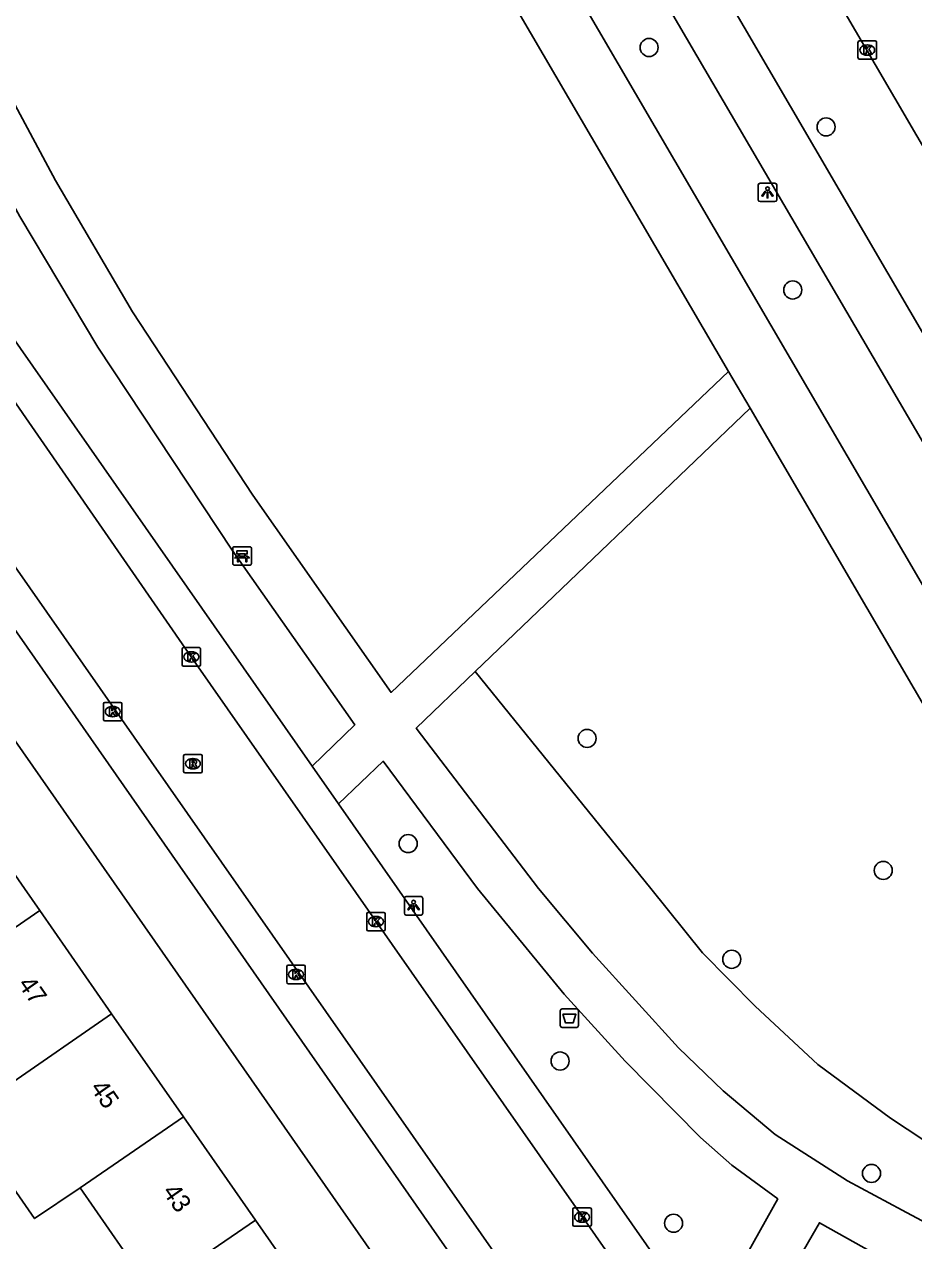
# Model space of a CAD drawing. Extents: x 159353 to 160616, y 385893 to 387321.
# Drawn here: x 159867.4 to 159915.6, y 386230.9 to 386296.8 of the extents above; entities that cross this region are included whole.
import ezdxf

# ---------------------------------------------------------------- set-up
doc = ezdxf.new("R2010")
doc.units = 0
for name, color, linetype in [('IMGEO_Afvalbak', 7, 'Continuous'), ('IMGEO_Bank', 7, 'Continuous'), ('IMGEO_Boom', 7, 'Continuous'), ('IMGEO_Fietspad_gesloten', 7, 'Continuous'), ('IMGEO_Groenvoorziening', 7, 'Continuous'), ('IMGEO_Kolk', 7, 'Continuous'), ('IMGEO_Lichtpunt', 7, 'Continuous'), ('IMGEO_Pand', 7, 'Continuous'), ('IMGEO_Pand_nummerreeks', 7, 'Continuous'), ('IMGEO_Rijbaan_lokaal_gesloten', 7, 'Continuous'), ('IMGEO_Rijbaan_lokaal_open', 7, 'Continuous'), ('IMGEO_Rioolput', 7, 'Continuous'), ('IMGEO_Voetpad_halfverhard', 7, 'Continuous'), ('IMGEO_Voetpad_open', 7, 'Continuous')]:
    doc.layers.add(name, color=color, linetype=linetype)

msp = doc.modelspace()

# ---------------------------------------------------------------- linework, layer by layer
at = {"layer": 'IMGEO_Afvalbak'}
for p, q in [((159896.459, 386242.574), (159896.459, 386243.374)), ((159896.459, 386243.374), (159896.459, 386242.574)), ((159896.559, 386243.474), (159897.349, 386243.474)), ((159897.349, 386243.474), (159896.559, 386243.474)), ((159897.449, 386243.374), (159897.449, 386242.574)), ((159897.449, 386242.574), (159897.449, 386243.374)), ((159897.349, 386242.474), (159896.559, 386242.474)), ((159896.559, 386242.474), (159897.349, 386242.474))]:
    msp.add_line(p, q, dxfattribs=at)
msp.add_lwpolyline([(159896.602, 386243.188), (159897.306, 386243.188), (159897.157, 386242.718), (159896.751, 386242.718), (159896.602, 386243.188)], dxfattribs=at)
for centre, start, end in [((159896.559, 386243.374), 90, 180), ((159896.559, 386243.374), 90, 180), ((159897.349, 386243.374), 0, 90), ((159897.349, 386243.374), 360, 90), ((159896.559, 386242.574), 180, 270), ((159896.559, 386242.574), 180, 270), ((159897.349, 386242.574), 270, 0), ((159897.349, 386242.574), 270, 0)]:
    msp.add_arc(centre, 0.1, start, end, dxfattribs=at)
at = {"layer": 'IMGEO_Bank'}
for p, q in [((159878.733, 386267.573), (159878.733, 386268.414)), ((159878.733, 386268.414), (159878.733, 386267.573)), ((159878.808, 386268.498), (159879.649, 386268.498)), ((159879.649, 386268.498), (159878.808, 386268.498)), ((159879.042, 386268.004), (159879.042, 386268.11)), ((159879.086, 386268.11), (159879.086, 386268.004)), ((159879.374, 386268.116), (159879.092, 386268.116)), ((159879.38, 386268.004), (159879.38, 386268.11)), ((159879.424, 386268.11), (159879.424, 386268.004)), ((159879.733, 386268.423), (159879.733, 386267.582)), ((159879.733, 386267.582), (159879.733, 386268.423)), ((159879.658, 386267.498), (159878.817, 386267.498)), ((159878.817, 386267.498), (159879.658, 386267.498)), ((159879.43, 386267.896), (159879.037, 386267.896)), ((159879.092, 386267.998), (159879.374, 386267.998))]:
    msp.add_line(p, q, dxfattribs=at)
for points in [[(159879.036, 386268.116), (159878.95, 386268.116), (159878.95, 386268.277), (159879.513, 386268.277), (159879.513, 386268.116), (159879.43, 386268.116)], [(159878.98, 386267.896), (159878.838, 386267.896), (159878.95, 386267.998), (159879.036, 386267.998)], [(159879.03, 386267.889), (159879.03, 386267.682), (159878.987, 386267.682), (159878.987, 386267.889)], [(159879.43, 386267.998), (159879.513, 386267.998), (159879.625, 386267.896), (159879.486, 386267.896)], [(159879.48, 386267.889), (159879.48, 386267.682), (159879.436, 386267.682), (159879.436, 386267.889)]]:
    msp.add_lwpolyline(points, dxfattribs=at)
for centre, radius, start, end in [((159878.811, 386268.42), 0.0779, 92.4484, 184.28452), ((159878.811, 386268.42), 0.0779, 92.4484, 184.28452), ((159879.035, 386268.109), 0.00671, 2.89567, 87.10433), ((159879.092, 386268.109), 0.00671, 92.89567, 177.10433), ((159879.374, 386268.109), 0.00671, 2.89567, 87.10433), ((159879.431, 386268.109), 0.00671, 92.89567, 177.10433), ((159879.655, 386268.42), 0.0779, 2.4484, 94.28452), ((159879.655, 386268.42), 0.0779, 2.4484, 94.28452), ((159878.811, 386267.576), 0.0779, 182.4484, 274.28452), ((159878.811, 386267.576), 0.0779, 182.4484, 274.28452), ((159878.98, 386267.889), 0.00671, 2.89567, 87.10433), ((159879.037, 386267.889), 0.00671, 92.89567, 177.10433), ((159879.035, 386268.005), 0.00671, 272.89567, 357.10433), ((159879.092, 386268.005), 0.00671, 182.89567, 267.10433), ((159879.374, 386268.005), 0.00671, 272.89567, 357.10433), ((159879.431, 386268.005), 0.00671, 182.89567, 267.10433), ((159879.429, 386267.889), 0.00671, 2.89567, 87.10433), ((159879.486, 386267.889), 0.00671, 92.89567, 177.10433), ((159879.655, 386267.576), 0.0779, 272.4484, 4.28452), ((159879.655, 386267.576), 0.0779, 272.4484, 4.28452)]:
    msp.add_arc(centre, radius, start, end, dxfattribs=at)
at = {"layer": 'IMGEO_Boom'}
for centre in [(159901.274, 386295.532), (159910.857, 386291.236), (159909.052, 386282.404), (159897.915, 386258.123), (159888.224, 386252.427), (159913.95, 386250.975), (159905.747, 386246.163), (159896.451, 386240.656), (159913.315, 386234.572), (159902.594, 386231.876)]:
    msp.add_circle(centre, 0.489, dxfattribs=at)
at = {"layer": 'IMGEO_Fietspad_gesloten'}
for points in [[(159847.159, 386392.191), (159854.556, 386379.293), (159862.352, 386365.974), (159919.537, 386268.282), (159935.204, 386241.272), (159944.825, 386225.156)], [(159947.456, 386226.623), (159938.723, 386241.317), (159864.988, 386367.537), (159851.28, 386391.003)]]:
    msp.add_lwpolyline(points, dxfattribs=at)
at = {"layer": 'IMGEO_Groenvoorziening'}
msp.add_lwpolyline([(159891.85, 386261.746), (159901.36, 386250), (159904.16, 386246.512), (159907.02, 386243.621), (159910.412, 386240.474), (159914.35, 386237.566), (159917.101, 386235.732), (159925.757, 386231.572), (159930.443, 386229.994), (159931.877, 386228.511), (159931.382, 386225.811)], dxfattribs=at)
at = {"layer": 'IMGEO_Kolk'}
for p, q in [((159912.583, 386294.969), (159912.583, 386295.821)), ((159912.658, 386295.895), (159913.51, 386295.895)), ((159913.584, 386295.821), (159913.584, 386294.969)), ((159913.094, 386295.115), (159913.069, 386295.115)), ((159913.071, 386295.675), (159913.096, 386295.675)), ((159913.51, 386294.895), (159912.658, 386294.895)), ((159875.98, 386262.113), (159875.98, 386262.965)), ((159876.055, 386263.039), (159876.907, 386263.039)), ((159876.468, 386262.819), (159876.493, 386262.819)), ((159876.981, 386262.965), (159876.981, 386262.113)), ((159876.491, 386262.259), (159876.466, 386262.259)), ((159876.907, 386262.039), (159876.055, 386262.039)), ((159871.726, 386259.149), (159871.726, 386260.001)), ((159871.801, 386260.075), (159872.653, 386260.075)), ((159872.214, 386259.855), (159872.239, 386259.855)), ((159872.727, 386260.001), (159872.727, 386259.149)), ((159872.653, 386259.075), (159871.801, 386259.075)), ((159872.237, 386259.295), (159872.212, 386259.295)), ((159885.98, 386247.78), (159885.98, 386248.632)), ((159886.055, 386248.706), (159886.907, 386248.706)), ((159886.468, 386248.486), (159886.493, 386248.486)), ((159886.981, 386248.632), (159886.981, 386247.78)), ((159886.907, 386247.706), (159886.055, 386247.706)), ((159886.491, 386247.926), (159886.466, 386247.926)), ((159881.653, 386244.917), (159881.653, 386245.769)), ((159881.728, 386245.843), (159882.58, 386245.843)), ((159882.654, 386245.769), (159882.654, 386244.917)), ((159882.164, 386245.063), (159882.139, 386245.063)), ((159882.141, 386245.623), (159882.166, 386245.623)), ((159882.58, 386244.843), (159881.728, 386244.843)), ((159897.143, 386231.781), (159897.143, 386232.633)), ((159897.218, 386232.707), (159898.07, 386232.707)), ((159898.144, 386232.633), (159898.144, 386231.781)), ((159897.654, 386231.927), (159897.629, 386231.927)), ((159897.631, 386232.487), (159897.656, 386232.487)), ((159898.07, 386231.707), (159897.218, 386231.707))]:
    msp.add_line(p, q, dxfattribs=at)
for points in [[(159912.583, 386294.969), (159912.583, 386295.821)], [(159912.658, 386295.895), (159913.51, 386295.895)], [(159913.584, 386295.821), (159913.584, 386294.969)], [(159912.904, 386295.595), (159913.027, 386295.595), (159913.027, 386295.444), (159913.157, 386295.595), (159913.321, 386295.595), (159913.175, 386295.444), (159913.328, 386295.195), (159913.176, 386295.195), (159913.091, 386295.359), (159913.027, 386295.292), (159913.027, 386295.195), (159912.904, 386295.195), (159912.904, 386295.595)], [(159913.51, 386294.895), (159912.658, 386294.895)], [(159875.98, 386262.113), (159875.98, 386262.965)], [(159876.055, 386263.039), (159876.907, 386263.039)], [(159876.981, 386262.965), (159876.981, 386262.113)], [(159876.301, 386262.739), (159876.424, 386262.739), (159876.424, 386262.588), (159876.554, 386262.739), (159876.718, 386262.739), (159876.572, 386262.588), (159876.725, 386262.339), (159876.573, 386262.339), (159876.488, 386262.503), (159876.424, 386262.436), (159876.424, 386262.339), (159876.301, 386262.339), (159876.301, 386262.739)], [(159876.907, 386262.039), (159876.055, 386262.039)], [(159871.726, 386259.149), (159871.726, 386260.001)], [(159871.801, 386260.075), (159872.653, 386260.075)], [(159872.047, 386259.775), (159872.17, 386259.775), (159872.17, 386259.624), (159872.3, 386259.775), (159872.464, 386259.775), (159872.318, 386259.624), (159872.471, 386259.375), (159872.319, 386259.375), (159872.234, 386259.539), (159872.17, 386259.472), (159872.17, 386259.375), (159872.047, 386259.375), (159872.047, 386259.775)], [(159872.727, 386260.001), (159872.727, 386259.149)], [(159872.653, 386259.075), (159871.801, 386259.075)], [(159885.98, 386247.78), (159885.98, 386248.632)], [(159886.055, 386248.706), (159886.907, 386248.706)], [(159886.301, 386248.406), (159886.424, 386248.406), (159886.424, 386248.255), (159886.554, 386248.406), (159886.718, 386248.406), (159886.572, 386248.255), (159886.725, 386248.006), (159886.573, 386248.006), (159886.488, 386248.17), (159886.424, 386248.103), (159886.424, 386248.006), (159886.301, 386248.006), (159886.301, 386248.406)], [(159886.981, 386248.632), (159886.981, 386247.78)], [(159886.907, 386247.706), (159886.055, 386247.706)], [(159881.653, 386244.917), (159881.653, 386245.769)], [(159881.728, 386245.843), (159882.58, 386245.843)], [(159882.654, 386245.769), (159882.654, 386244.917)], [(159881.974, 386245.543), (159882.097, 386245.543), (159882.097, 386245.392), (159882.227, 386245.543), (159882.391, 386245.543), (159882.245, 386245.392), (159882.398, 386245.143), (159882.246, 386245.143), (159882.161, 386245.307), (159882.097, 386245.24), (159882.097, 386245.143), (159881.974, 386245.143), (159881.974, 386245.543)], [(159882.58, 386244.843), (159881.728, 386244.843)], [(159897.143, 386231.781), (159897.143, 386232.633)], [(159897.218, 386232.707), (159898.07, 386232.707)], [(159898.144, 386232.633), (159898.144, 386231.781)], [(159897.464, 386232.407), (159897.587, 386232.407), (159897.587, 386232.256), (159897.717, 386232.407), (159897.881, 386232.407), (159897.735, 386232.256), (159897.888, 386232.007), (159897.736, 386232.007), (159897.651, 386232.171), (159897.587, 386232.104), (159897.587, 386232.007), (159897.464, 386232.007), (159897.464, 386232.407)], [(159898.07, 386231.707), (159897.218, 386231.707)]]:
    msp.add_lwpolyline(points, dxfattribs=at)
for centre, start, end in [((159912.66, 386295.819), 91.55205, 178.44795), ((159912.66, 386295.819), 91.55205, 178.44795), ((159913.508, 386295.819), 1.55205, 88.44795), ((159913.508, 386295.819), 1.55205, 88.44795), ((159912.66, 386294.971), 181.55205, 268.44795), ((159912.66, 386294.971), 181.55205, 268.44795), ((159913.508, 386294.971), 271.55205, 358.44795), ((159913.508, 386294.971), 271.55205, 358.44795), ((159876.057, 386262.963), 91.55205, 178.44795), ((159876.057, 386262.963), 91.55205, 178.44795), ((159876.905, 386262.963), 1.55205, 88.44795), ((159876.905, 386262.963), 1.55205, 88.44795), ((159876.057, 386262.115), 181.55205, 268.44795), ((159876.057, 386262.115), 181.55205, 268.44795), ((159876.905, 386262.115), 271.55205, 358.44795), ((159876.905, 386262.115), 271.55205, 358.44795), ((159871.803, 386259.999), 91.55205, 178.44795), ((159871.803, 386259.999), 91.55205, 178.44795), ((159872.651, 386259.999), 1.55205, 88.44795), ((159872.651, 386259.999), 1.55205, 88.44795), ((159871.803, 386259.151), 181.55205, 268.44795), ((159871.803, 386259.151), 181.55205, 268.44795), ((159872.651, 386259.151), 271.55205, 358.44795), ((159872.651, 386259.151), 271.55205, 358.44795), ((159886.057, 386248.63), 91.55205, 178.44795), ((159886.057, 386248.63), 91.55205, 178.44795), ((159886.905, 386248.63), 1.55205, 88.44795), ((159886.905, 386248.63), 1.55205, 88.44795), ((159886.057, 386247.782), 181.55205, 268.44795), ((159886.057, 386247.782), 181.55205, 268.44795), ((159886.905, 386247.782), 271.55205, 358.44795), ((159886.905, 386247.782), 271.55205, 358.44795), ((159881.73, 386245.767), 91.55205, 178.44795), ((159881.73, 386245.767), 91.55205, 178.44795), ((159882.578, 386245.767), 1.55205, 88.44795), ((159882.578, 386245.767), 1.55205, 88.44795), ((159881.73, 386244.919), 181.55205, 268.44795), ((159881.73, 386244.919), 181.55205, 268.44795), ((159882.578, 386244.919), 271.55205, 358.44795), ((159882.578, 386244.919), 271.55205, 358.44795), ((159897.22, 386232.631), 91.55205, 178.44795), ((159897.22, 386232.631), 91.55205, 178.44795), ((159898.068, 386232.631), 1.55205, 88.44795), ((159898.068, 386232.631), 1.55205, 88.44795), ((159897.22, 386231.783), 181.55205, 268.44795), ((159897.22, 386231.783), 181.55205, 268.44795), ((159898.068, 386231.783), 271.55205, 358.44795), ((159898.068, 386231.783), 271.55205, 358.44795)]:
    msp.add_arc(centre, 0.0765, start, end, dxfattribs=at)
for centre, major_axis, ratio, start_param, end_param in [((159913.07, 386295.395), (-0.387, 0.002), 0.722429, 4.712389, 7.853982), ((159913.095, 386295.395), (-0.39, 0.002), 0.717154, 1.570796, 4.712389), ((159876.467, 386262.539), (-0.387, 0.002), 0.722429, 4.712389, 7.853982), ((159876.492, 386262.539), (-0.39, 0.002), 0.717154, 1.570796, 4.712389), ((159872.213, 386259.575), (-0.387, 0.002), 0.722429, 4.712389, 7.853982), ((159872.238, 386259.575), (-0.39, 0.002), 0.717154, 1.570796, 4.712389), ((159886.467, 386248.206), (-0.387, 0.002), 0.722429, 4.712389, 7.853982), ((159886.492, 386248.206), (-0.39, 0.002), 0.717154, 1.570796, 4.712389), ((159882.14, 386245.343), (-0.387, 0.002), 0.722429, 4.712389, 7.853982), ((159882.165, 386245.343), (-0.39, 0.002), 0.717154, 1.570796, 4.712389), ((159897.63, 386232.207), (-0.387, 0.002), 0.722429, 4.712389, 7.853982), ((159897.655, 386232.207), (-0.39, 0.002), 0.717154, 1.570796, 4.712389)]:
    msp.add_ellipse(centre, major_axis=major_axis, ratio=ratio, start_param=start_param, end_param=end_param, dxfattribs=at)
at = {"layer": 'IMGEO_Lichtpunt'}
for p, q in [((159907.184, 386288.092), (159907.184, 386287.285)), ((159907.184, 386288.092), (159907.184, 386287.285)), ((159908.086, 386288.187), (159907.278, 386288.187)), ((159908.086, 386288.187), (159907.278, 386288.187)), ((159908.18, 386287.285), (159908.18, 386288.092)), ((159908.18, 386287.285), (159908.18, 386288.092)), ((159907.278, 386287.191), (159908.086, 386287.191)), ((159907.278, 386287.191), (159908.086, 386287.191)), ((159888.019, 386249.461), (159888.019, 386248.654)), ((159888.019, 386249.461), (159888.019, 386248.654)), ((159888.921, 386249.556), (159888.113, 386249.556)), ((159888.921, 386249.556), (159888.113, 386249.556)), ((159889.015, 386248.654), (159889.015, 386249.461)), ((159889.015, 386248.654), (159889.015, 386249.461)), ((159888.113, 386248.56), (159888.921, 386248.56)), ((159888.113, 386248.56), (159888.921, 386248.56))]:
    msp.add_line(p, q, dxfattribs=at)
for points in [[(159907.558, 386287.756), (159907.597, 386287.728), (159907.409, 386287.466), (159907.371, 386287.493), (159907.558, 386287.756)], [(159907.66, 386287.708), (159907.707, 386287.708), (159907.707, 386287.386), (159907.66, 386287.386), (159907.66, 386287.708)], [(159907.77, 386287.728), (159907.808, 386287.755), (159907.995, 386287.493), (159907.956, 386287.465), (159907.77, 386287.728)], [(159888.393, 386249.125), (159888.432, 386249.097), (159888.244, 386248.835), (159888.206, 386248.862), (159888.393, 386249.125)], [(159888.495, 386249.077), (159888.542, 386249.077), (159888.542, 386248.755), (159888.495, 386248.755), (159888.495, 386249.077)], [(159888.605, 386249.097), (159888.643, 386249.124), (159888.83, 386248.862), (159888.791, 386248.834), (159888.605, 386249.097)]]:
    msp.add_lwpolyline(points, dxfattribs=at)
for centre in [(159907.683, 386287.89), (159888.518, 386249.259)]:
    msp.add_circle(centre, 0.0994, dxfattribs=at)
for centre, start, end in [((159907.278, 386288.092), 90, 180), ((159907.278, 386288.092), 90, 180), ((159908.086, 386288.092), 0, 90), ((159908.086, 386288.092), 0, 90), ((159907.278, 386287.285), 180, 270), ((159907.278, 386287.285), 180, 270), ((159908.086, 386287.285), 270, 0), ((159908.086, 386287.285), 270, 360), ((159888.113, 386249.461), 90, 180), ((159888.113, 386249.461), 90, 180), ((159888.921, 386249.461), 0, 90), ((159888.921, 386249.461), 0, 90), ((159888.113, 386248.654), 180, 270), ((159888.113, 386248.654), 180, 270), ((159888.921, 386248.654), 270, 0), ((159888.921, 386248.654), 270, 360)]:
    msp.add_arc(centre, 0.0946, start, end, dxfattribs=at)
at = {"layer": 'IMGEO_Pand'}
for points in [[(159864.38, 386254.395), (159867.442, 386250), (159868.273, 386248.807)], [(159868.273, 386248.807), (159862.69, 386244.961), (159860.22, 386243.199)], [(159868.273, 386248.807), (159872.166, 386243.219)], [(159872.166, 386243.219), (159866.587, 386239.358)], [(159872.166, 386243.219), (159876.059, 386237.63)], [(159870.464, 386233.785), (159867.994, 386232.122), (159864.156, 386237.639), (159866.587, 386239.358)], [(159876.059, 386237.63), (159870.464, 386233.785)], [(159876.059, 386237.63), (159879.953, 386232.041)], [(159874.349, 386228.2), (159870.464, 386233.785)], [(159874.349, 386228.2), (159879.953, 386232.041)], [(159879.953, 386232.041), (159883.85, 386226.448)]]:
    msp.add_lwpolyline(points, dxfattribs=at)
at = {"layer": 'IMGEO_Rijbaan_lokaal_gesloten'}
msp.add_lwpolyline([(159858.158, 386389.37), (159869.39, 386370.145), (159949.928, 386232.299)], dxfattribs=at)
at = {"layer": 'IMGEO_Rijbaan_lokaal_open'}
for points in [[(159865.171, 386278.695), (159866.503, 386276.943), (159876.481, 386262.539), (159915.274, 386207.012)], [(159861.15, 386275.683), (159896.906, 386224.528)]]:
    msp.add_lwpolyline(points, dxfattribs=at)
at = {"layer": 'IMGEO_Rioolput'}
for p, q in [((159876.066, 386256.329), (159876.066, 386257.181)), ((159876.141, 386257.255), (159876.993, 386257.255)), ((159876.554, 386257.035), (159876.579, 386257.035)), ((159877.067, 386257.181), (159877.067, 386256.329)), ((159876.993, 386256.255), (159876.141, 386256.255)), ((159876.577, 386256.475), (159876.552, 386256.475))]:
    msp.add_line(p, q, dxfattribs=at)
for points in [[(159876.066, 386256.329), (159876.066, 386257.181)], [(159876.141, 386257.255), (159876.993, 386257.255)], [(159876.655, 386256.953), (159876.403, 386256.955), (159876.403, 386256.555)], [(159876.581, 386256.874), (159876.527, 386256.874), (159876.527, 386256.793)], [(159877.067, 386257.181), (159877.067, 386256.329)], [(159876.993, 386256.255), (159876.141, 386256.255)], [(159876.403, 386256.555), (159876.527, 386256.555), (159876.527, 386256.717), (159876.538, 386256.717)], [(159876.527, 386256.793), (159876.579, 386256.793)], [(159876.585, 386256.688), (159876.656, 386256.555), (159876.796, 386256.555), (159876.731, 386256.681)]]:
    msp.add_lwpolyline(points, dxfattribs=at)
for centre, radius, start, end in [((159876.143, 386257.179), 0.0765, 91.55205, 178.44795), ((159876.143, 386257.179), 0.0765, 91.55205, 178.44795), ((159876.587, 386256.778), 0.0964, 77.00612, 93.18647), ((159876.601, 386256.835), 0.0378, 276.66336, 79.67722), ((159876.654, 386256.843), 0.109, 350.36119, 89.41601), ((159876.991, 386257.179), 0.0765, 1.55205, 88.44795), ((159876.991, 386257.179), 0.0765, 1.55205, 88.44795), ((159876.143, 386256.331), 0.0765, 181.55205, 268.44795), ((159876.143, 386256.331), 0.0765, 181.55205, 268.44795), ((159876.537, 386256.664), 0.0533, 26.02933, 88.69889), ((159876.563, 386256.982), 0.19, 274.7715, 282.96867), ((159876.652, 386256.843), 0.112, 277.58423, 350.98172), ((159876.636, 386256.628), 0.108, 29.51342, 73.79051), ((159876.991, 386256.331), 0.0765, 271.55205, 358.44795), ((159876.991, 386256.331), 0.0765, 271.55205, 358.44795)]:
    msp.add_arc(centre, radius, start, end, dxfattribs=at)
for centre, major_axis, ratio, start_param, end_param in [((159876.553, 386256.755), (-0.387, 0.002), 0.722429, 4.712389, 7.853982), ((159876.578, 386256.755), (-0.39, 0.002), 0.717154, 1.570796, 4.712389)]:
    msp.add_ellipse(centre, major_axis=major_axis, ratio=ratio, start_param=start_param, end_param=end_param, dxfattribs=at)
at = {"layer": 'IMGEO_Voetpad_halfverhard'}
for points in [[(159905.576, 386277.985), (159887.302, 386260.612), (159879.815, 386271.298), (159873.288, 386281.214), (159869.124, 386288.336), (159858.278, 386308.583)], [(159856.552, 386306.402), (159863.643, 386292.837), (159867.197, 386286.374), (159871.413, 386279.303), (159878.699, 386268.318), (159885.335, 386258.851), (159883.019, 386256.63)], [(159891.85, 386261.746), (159906.737, 386276.003)], [(159920.313, 386229.728), (159914.98, 386232.579), (159912.009, 386234.168), (159908.09, 386236.682), (159905.29, 386239.038), (159902.869, 386241.374), (159898.198, 386246.494), (159895.276, 386250), (159888.662, 386258.685), (159891.85, 386261.746)], [(159884.445, 386254.589), (159886.876, 386256.884), (159891.975, 386250), (159896.671, 386244.284), (159899.972, 386240.64), (159904.063, 386236.518), (159905.754, 386235.021), (159908.234, 386233.194), (159904.311, 386226.148)], [(159905.885, 386223.895), (159907.972, 386227.52), (159910.493, 386231.898), (159915.332, 386229.185), (159921.588, 386226.114)]]:
    msp.add_lwpolyline(points, dxfattribs=at)
at = {"layer": 'IMGEO_Voetpad_open'}
for points in [[(159944.825, 386225.156), (159941.411, 386223.11), (159926.534, 386248.554), (159859.054, 386364.02), (159843.747, 386390.213), (159847.159, 386392.191)], [(159876.401, 386327.92), (159884.135, 386314.683), (159905.576, 386277.985)], [(159883.019, 386256.63), (159852.087, 386300.915)], [(159905.576, 386277.985), (159906.737, 386276.003)], [(159890.682, 386220.04), (159892.54, 386221.275), (159853.707, 386276.934)], [(159906.737, 386276.003), (159921.946, 386250), (159936.607, 386224.933)], [(159893.478, 386225.933), (159861.381, 386271.944)], [(159884.445, 386254.589), (159883.019, 386256.63)], [(159904.311, 386226.148), (159884.445, 386254.589)]]:
    msp.add_lwpolyline(points, dxfattribs=at)

# ---------------------------------------------------------------- texts
at = {"layer": 'IMGEO_Pand_nummerreeks'}
for s, p in [('47', (159867.057, 386244.815)), ('45', (159870.969, 386239.199)), ('43', (159874.882, 386233.583))]:
    msp.add_text(s, height=1, rotation=304.86386, dxfattribs=at).set_placement(p)

doc.saveas('drawing.dxf')
